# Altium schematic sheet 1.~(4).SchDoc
size 420 x 297 mm
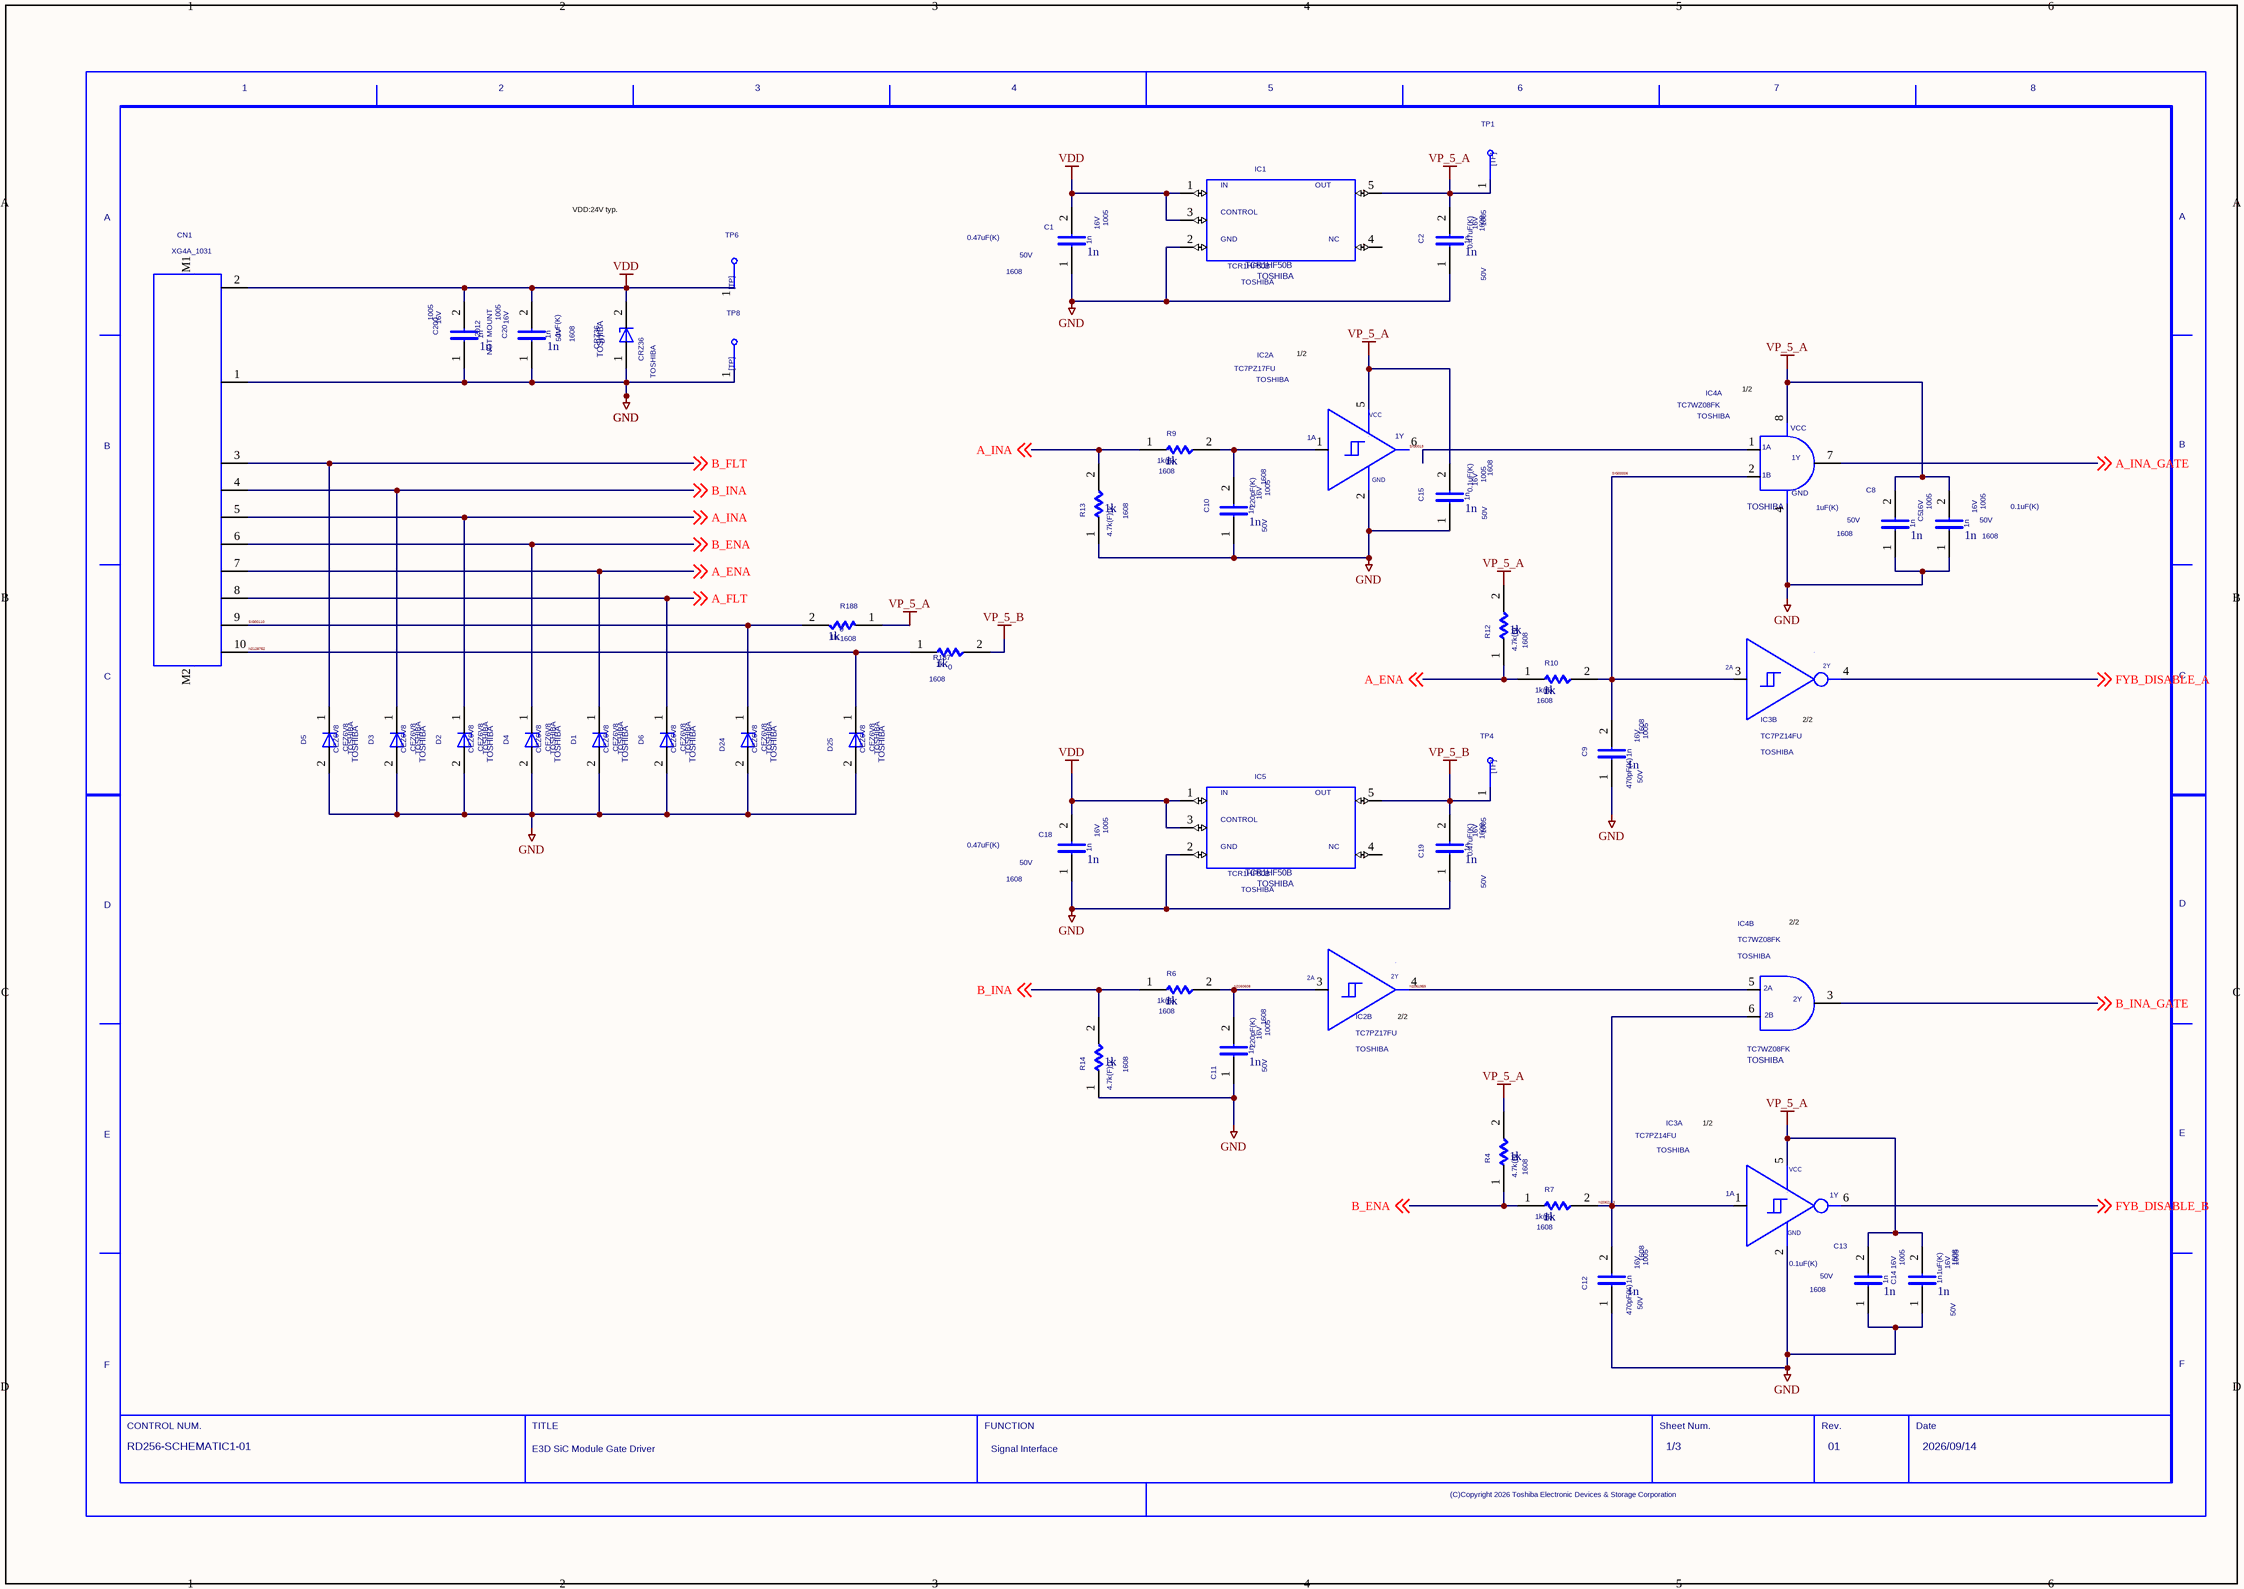
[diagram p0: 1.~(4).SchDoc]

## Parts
C1  1n  VAL1: 0.47uF(K)  SIZE: 1005  VOLTAGE: 16V  SIZECODESMD: 1608  VAL2: 50V
C2  1n  VAL1: 0.47uF(K)  SIZE: 1005  VOLTAGE: 16V  SIZECODESMD: 1608  VAL2: 50V
C5  1n  VAL1: 0.1uF(K)  SIZE: 1005  VOLTAGE: 16V  SIZECODESMD: 1608  VAL2: 50V
C8  1n  VAL1: 1uF(K)  SIZE: 1005  VOLTAGE: 16V  SIZECODESMD: 1608  VAL2: 50V
C9  1n  VAL1: 470pF(K)  SIZE: 1005  VOLTAGE: 16V  SIZECODESMD: 1608  VAL2: 50V
C10  1n  VAL1: 220pF(K)  SIZE: 1005  VOLTAGE: 16V  SIZECODESMD: 1608  VAL2: 50V
C11  1n  VAL1: 220pF(K)  SIZE: 1005  VOLTAGE: 16V  SIZECODESMD: 1608  VAL2: 50V
C12  1n  VAL1: 470pF(K)  SIZE: 1005  VOLTAGE: 16V  SIZECODESMD: 1608  VAL2: 50V
C13  1n  VAL1: 0.1uF(K)  SIZE: 1005  VOLTAGE: 16V  SIZECODESMD: 1608  VAL2: 50V
C14  1n  VAL1: 1uF(K)  SIZE: 1005  VOLTAGE: 16V  SIZECODESMD: 1608  VAL2: 50V
C15  1n  VAL1: 0.1uF(K)  SIZE: 1005  VOLTAGE: 16V  SIZECODESMD: 1608  VAL2: 50V
C18  1n  VAL1: 0.47uF(K)  SIZE: 1005  VOLTAGE: 16V  SIZECODESMD: 1608  VAL2: 50V
C19  1n  VAL1: 0.47uF(K)  SIZE: 1005  VOLTAGE: 16V  SIZECODESMD: 1608  VAL2: 50V
C20  1n  VAL1: 1uF(K)  SIZE: 1005  VOLTAGE: 16V  SIZECODESMD: 1608  VAL2: 50V
C200  1n  SIZE: 1005  VOLTAGE: 16V  SIZECODESMD: 2012  NOTMOUNT: NOT MOUNT
CN1  XG4A_1031
D1  CEZ6V8  VENDOR: TOSHIBA
D2  CEZ6V8  VENDOR: TOSHIBA
D3  CEZ6V8  VENDOR: TOSHIBA
D4  CEZ6V8  VENDOR: TOSHIBA
D5  CEZ6V8  VENDOR: TOSHIBA
D6  CEZ6V8  VENDOR: TOSHIBA
D7  CRZ36  VENDOR: TOSHIBA
D24  CEZ6V8  VENDOR: TOSHIBA
D25  CEZ6V8  VENDOR: TOSHIBA
IC1  TCR1HF50B  VENDOR: TOSHIBA
IC2  USERCOMPTEXT3: TOSHIBA  (hidden comment: TC7PZ17FU)  (parts A,B of 2)
IC3  USERCOMPTEXT3: TOSHIBA  VAL3: TC7PZ14FU  (hidden comment: TC7PZ17FU)  (parts A,B of 2)
IC4  VENDOR: TOSHIBA  (hidden comment: TC7WZ08FK)  (parts A,B of 2)
IC5  TCR1HF50B  VENDOR: TOSHIBA
R4  1k  VAL1: 4.7k(F)  SIZECODESMD: 1608
R6  1k  VAL1: 1k(F)  SIZECODESMD: 1608
R7  1k  VAL1: 1k(F)  SIZECODESMD: 1608
R9  1k  VAL1: 1k(F)  SIZECODESMD: 1608
R10  1k  VAL1: 1k(F)  SIZECODESMD: 1608
R12  1k  VAL1: 4.7k(F)  SIZECODESMD: 1608
R13  1k  VAL1: 4.7k(F)  SIZECODESMD: 1608
R14  1k  VAL1: 4.7k(F)  SIZECODESMD: 1608
R187  1k  VAL1: 0  SIZECODESMD: 1608
R188  1k  VAL1: 0  SIZECODESMD: 1608
TP1  TP  (value not drawn)
TP4  TP  (value not drawn)
TP6  TP  (value not drawn)
TP8  TP  (value not drawn)
U?  DATE: 2026/09/14  DRAWINGNUMBER: RD256-SCHEMATIC1-01  TITLE: E3D SiC Module Gate Driver  FUNCTION: Signal Interface  SHEETNUMBER: 1/3  REVISION: 01  (hidden comment: WAKU_DEF100)

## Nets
GND: C1.1 C2.1 C5.1 C8.1 C9.1 C10.1 C11.1 C12.1 C13.1 C14.1 C15.1 C18.1 C19.1 C20.1 C200.1 CN1.1 D1.2(A) D2.2(A) D3.2(A) D4.2(A) D5.2(A) D6.2(A) D7.1(A) D24.2(A) D25.2(A) IC1.2 IC2.2 IC3.2 IC4.4 IC5.2 R13.1 R14.1 TP8.1
VDD: C1.2 C18.2 C20.2 C200.2 CN1.2 D7.2(C) IC1.1 IC1.3 IC5.1 IC5.3 TP6.1
VP_5_A: C2.2 C5.2 C8.2 C13.2 C14.2 C15.2 IC1.5 IC2.5 IC3.5 IC4.8 R4.2 R12.2 R188.1 TP1.1
VP_5_B: C19.2 IC5.5 R187.2 TP4.1
A_ENA: CN1.7 D1.1(C) R10.1 R12.1 ; off-sheet A_ENA
A_FLT: CN1.8 D6.1(C) ; off-sheet A_FLT
A_INA: CN1.5 D2.1(C) R9.1 R13.2 ; off-sheet A_INA
A_INA_GATE: IC4.7 ; off-sheet A_INA_GATE
B_ENA: CN1.6 D4.1(C) R4.1 R7.1 ; off-sheet B_ENA
B_FLT: CN1.3 D5.1(C) ; off-sheet B_FLT
B_INA: CN1.4 D3.1(C) R6.1 R14.2 ; off-sheet B_INA
B_INA_GATE: IC4.3 ; off-sheet B_INA_GATE
FYB_DISABLE_A: IC3.4 ; off-sheet FYB_DISABLE_A
FYB_DISABLE_B: IC3.6 ; off-sheet FYB_DISABLE_B
N2060608: C11.2 IC2.3 R6.2
N2061959: IC2.4 IC4.5
N2062113: C12.2 IC3.1 IC4.6 R7.2
N2128752: CN1.10 D25.1(C) R187.1
SIG00006: C9.2 IC3.3 IC4.2 R10.2
SIG0013: IC2.6
SIG00110: CN1.9 D24.1(C) R188.2
SIG00237: C10.2 IC2.1 R9.2

Not connected (* = marked no-connect by the designer): CN1 M1 M2; IC1 4; IC4 1; IC5 4

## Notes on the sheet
- VDD:24V typ.
- 1/2
- (near IC4) 1/2
- (near IC3) 2/2
- 2/2
- (near IC2) 2/2
- (near IC3) 1/2

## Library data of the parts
C1 C18 = C: TIME: 11:55:01; UPDATEUSER: HP_Z8_KEYSHOT; SAVECOUNT: 2; TC1: 0; PSPICETEMPLATE: C^@REFDES %1 %2 ?TOLERANCE¦C^@REFDES¦ @VALUE ?IC/IC=@IC/ TC=@TC1,@TC2 ?TOLERANCE¦\n.model C^@REFDES CAP C=1 DEV=@TOLERANCE% TC1=@TC1 TC2=@TC2 VC1=@VC1 VC2=@VC2¦; ORIGINALSYMBOLORIGIN: (0,0); INSTANCENAME: INS1386363
C2 C19 = C: TIME: 11:55:01; UPDATEUSER: HP_Z8_KEYSHOT; SAVECOUNT: 2; TC1: 0; PSPICETEMPLATE: C^@REFDES %1 %2 ?TOLERANCE¦C^@REFDES¦ @VALUE ?IC/IC=@IC/ TC=@TC1,@TC2 ?TOLERANCE¦\n.model C^@REFDES CAP C=1 DEV=@TOLERANCE% TC1=@TC1 TC2=@TC2 VC1=@VC1 VC2=@VC2¦; ORIGINALSYMBOLORIGIN: (0,0); INSTANCENAME: INS1386331
C5 C14 C15 = C: TIME: 11:55:01; UPDATEUSER: HP_Z8_KEYSHOT; SAVECOUNT: 2; TC1: 0; PSPICETEMPLATE: C^@REFDES %1 %2 ?TOLERANCE¦C^@REFDES¦ @VALUE ?IC/IC=@IC/ TC=@TC1,@TC2 ?TOLERANCE¦\n.model C^@REFDES CAP C=1 DEV=@TOLERANCE% TC1=@TC1 TC2=@TC2 VC1=@VC1 VC2=@VC2¦; ORIGINALSYMBOLORIGIN: (0,0); INSTANCENAME: INS1386793
C8 C13 = C: TIME: 11:55:01; UPDATEUSER: HP_Z8_KEYSHOT; SAVECOUNT: 2; TC1: 0; PSPICETEMPLATE: C^@REFDES %1 %2 ?TOLERANCE¦C^@REFDES¦ @VALUE ?IC/IC=@IC/ TC=@TC1,@TC2 ?TOLERANCE¦\n.model C^@REFDES CAP C=1 DEV=@TOLERANCE% TC1=@TC1 TC2=@TC2 VC1=@VC1 VC2=@VC2¦; ORIGINALSYMBOLORIGIN: (0,0); INSTANCENAME: INS1386091
C9 C12 = C: TIME: 11:55:01; UPDATEUSER: HP_Z8_KEYSHOT; SAVECOUNT: 2; TC1: 0; PSPICETEMPLATE: C^@REFDES %1 %2 ?TOLERANCE¦C^@REFDES¦ @VALUE ?IC/IC=@IC/ TC=@TC1,@TC2 ?TOLERANCE¦\n.model C^@REFDES CAP C=1 DEV=@TOLERANCE% TC1=@TC1 TC2=@TC2 VC1=@VC1 VC2=@VC2¦; ORIGINALSYMBOLORIGIN: (0,0); INSTANCENAME: INS1386155
C10 C11 = C: TIME: 11:55:01; UPDATEUSER: HP_Z8_KEYSHOT; SAVECOUNT: 2; TC1: 0; PSPICETEMPLATE: C^@REFDES %1 %2 ?TOLERANCE¦C^@REFDES¦ @VALUE ?IC/IC=@IC/ TC=@TC1,@TC2 ?TOLERANCE¦\n.model C^@REFDES CAP C=1 DEV=@TOLERANCE% TC1=@TC1 TC2=@TC2 VC1=@VC1 VC2=@VC2¦; ORIGINALSYMBOLORIGIN: (0,0); INSTANCENAME: INS1386019
C20 = C: TIME: 11:55:01; UPDATEUSER: HP_Z8_KEYSHOT; SAVECOUNT: 2; TC1: 0; PSPICETEMPLATE: C^@REFDES %1 %2 ?TOLERANCE¦C^@REFDES¦ @VALUE ?IC/IC=@IC/ TC=@TC1,@TC2 ?TOLERANCE¦\n.model C^@REFDES CAP C=1 DEV=@TOLERANCE% TC1=@TC1 TC2=@TC2 VC1=@VC1 VC2=@VC2¦; ORIGINALSYMBOLORIGIN: (0,0); INSTANCENAME: INS1386685
C200 = C: TIME: 11:55:01; UPDATEUSER: HP_Z8_KEYSHOT; SAVECOUNT: 2; TC1: 0; PSPICETEMPLATE: C^@REFDES %1 %2 ?TOLERANCE¦C^@REFDES¦ @VALUE ?IC/IC=@IC/ TC=@TC1,@TC2 ?TOLERANCE¦\n.model C^@REFDES CAP C=1 DEV=@TOLERANCE% TC1=@TC1 TC2=@TC2 VC1=@VC1 VC2=@VC2¦; ORIGINALSYMBOLORIGIN: (0,0); INSTANCENAME: INS2126613
CN1 = XG4A_1031_1: PART NUMBER: XG4A-1031; TIME: 11:54:59; UPDATEUSER: t5459927; UPDATETIME: 17:44:51; SAVECOUNT: 12; PSPICETEMPLATE: X^@REFDES %1 %2 %3 %4 %5 %6 %7 %8 %9 %10 %M1 %M2 @MODEL; OriginalSymbolOrigin: (0,73660)
D1-D6 D24 D25 = CEZ6V8: TIME: 14:49:55; UPDATEUSER: fukuda-y; UPDATETIME: 08:18:42; SAVECOUNT: 6; SAVEAREA0: -4630,-153,17114,13055; PSPICETEMPLATE: X^@REFDES %A %C @MODEL; ORIGINALSYMBOLORIGIN: (0,0); INSTANCENAME: INS1385789
D7 = CRZ36: TIME: 14:49:55; UPDATEUSER: fukuda-y; UPDATETIME: 08:18:42; SAVECOUNT: 6; SAVEAREA0: -4630,-153,17114,13055; PSPICETEMPLATE: X^@REFDES %A %C @MODEL; ORIGINALSYMBOLORIGIN: (0,0); INSTANCENAME: INS1385571
IC1 IC5 = TCR1HF50B: TIME: 11:54:59; UPDATEUSER: t5459927; UPDATETIME: 10:27:35; SAVECOUNT: 4; PSPICETEMPLATE: X^@REFDES %IN %GND %CONTROL %NC %OUT @MODEL; OriginalSymbolOrigin: (-2540,0); INSTANCENAME: INS1386243
IC2 = TC7PZ17FU_2: TIME: 11:55:01; UPDATEUSER: t5459927; UPDATETIME: 15:05:08; SAVECOUNT: 4; SPLIT_INST: TRUE; PSPICETEMPLATE: X^@REFDES %1A %GND %2A %2Y %VCC %1Y @MODEL; SWAP_INFO: (S1+S2); OriginalSymbolOrigin: (5080,15240); CaptureCellPackProp: TC7PZ17FU_2A; FUNCN: TC7PZ17FU_1; INSTANCENAME: INS2115366
IC3 = TC7PZ14FU_2: TIME: 11:55:01; UPDATEUSER: t5459927; UPDATETIME: 19:09:34; SAVECOUNT: 7; SPLIT_INST: TRUE; PSPICETEMPLATE: X^@REFDES %1A %GND %2A %2Y %VCC %1Y @MODEL; SWAP_INFO: (S1+S2); OriginalSymbolOrigin: (5080,15240); CaptureCellPackProp: TC7PZ14FU_2A; FUNCN: TC7PZ14FU_1; INSTANCENAME: INS2115979
IC4 = TC7WZ08FK_1: TIME: 08:52:39; UPDATEUSER: sptcae09; UPDATETIME: 16:09:46; SAVECOUNT: 9; SWAP_INFO: (S1+S2); ORDER: $pOrder; SPLIT_INST: TRUE; ・: 20mA; USER_VALUE: TC7W00FK; PSPICETEMPLATE: X^@REFDES %1A %1B %2Y %GND %2A %2B %1Y %VCC @MODEL; DESCRIPTION-A: NAND 2ch Logic; ORIGINALSYMBOLORIGIN: (2540,-2540); CaptureCellPackProp: TC7WZ08FK_1A; INSTANCENAME: INS2116618
R4 R6 R7 R9 R10 R12 = R_Dup1: TIME: 11:54:58; UPDATEUSER: HP_Z8_KEYSHOT; UPDATETIME: 11:54:59; SAVECOUNT: 2; WATT: 0.125; COMP: R; TC1: 0; PSPICETEMPLATE: R^@REFDES %1 %2 ?TOLERANCE¦R^@REFDES¦ @VALUE TC=@TC1,@TC2 ?TOLERANCE¦\n.model R^@REFDES RES R=1 DEV=@TOLERANCE% TC1=@TC1 TC2=@TC2¦; ORIGINALSYMBOLORIGIN: (0,0); VAL2: 100mW; INSTANCENAME: INS1387005
R13 R14 = R_Dup1: TIME: 11:54:58; UPDATEUSER: HP_Z8_KEYSHOT; UPDATETIME: 11:54:59; SAVECOUNT: 2; WATT: 0.125; COMP: R; TC1: 0; PSPICETEMPLATE: R^@REFDES %1 %2 ?TOLERANCE¦R^@REFDES¦ @VALUE TC=@TC1,@TC2 ?TOLERANCE¦\n.model R^@REFDES RES R=1 DEV=@TOLERANCE% TC1=@TC1 TC2=@TC2¦; ORIGINALSYMBOLORIGIN: (0,0); VAL2: 100mW; INSTANCENAME: INS2060849
R187 = R_Dup1: TIME: 11:54:58; UPDATEUSER: HP_Z8_KEYSHOT; UPDATETIME: 11:54:59; SAVECOUNT: 2; WATT: 0.125; COMP: R; PSPICETEMPLATE: R^@REFDES %1 %2 ?TOLERANCE¦R^@REFDES¦ @VALUE TC=@TC1,@TC2 ?TOLERANCE¦\n.model R^@REFDES RES R=1 DEV=@TOLERANCE% TC1=@TC1 TC2=@TC2¦; ORIGINALSYMBOLORIGIN: (0,0); INSTANCENAME: INS2126667
R188 = R_Dup1: TIME: 11:54:58; UPDATEUSER: HP_Z8_KEYSHOT; UPDATETIME: 11:54:59; SAVECOUNT: 2; WATT: 0.125; COMP: R; PSPICETEMPLATE: R^@REFDES %1 %2 ?TOLERANCE¦R^@REFDES¦ @VALUE TC=@TC1,@TC2 ?TOLERANCE¦\n.model R^@REFDES RES R=1 DEV=@TOLERANCE% TC1=@TC1 TC2=@TC2¦; ORIGINALSYMBOLORIGIN: (0,0); INSTANCENAME: INS2126643
TP1 = TP: TIME: 16:12:21; UPDATEUSER: fukuda-y; UPDATETIME: 16:18:11; SAVECOUNT: 2; SAVEAREA0: -242,-92,12810,7836; ORIGINALSYMBOLORIGIN: (0,0); INSTANCENAME: INS1385435
TP4 = TP: TIME: 16:12:21; UPDATEUSER: fukuda-y; UPDATETIME: 16:18:11; SAVECOUNT: 2; SAVEAREA0: -242,-92,12810,7836; ORIGINALSYMBOLORIGIN: (0,0); INSTANCENAME: INS2191044
TP6 = TP: TIME: 16:12:21; UPDATEUSER: fukuda-y; UPDATETIME: 16:18:11; SAVECOUNT: 2; SAVEAREA0: -242,-92,12810,7836; ORIGINALSYMBOLORIGIN: (0,0); INSTANCENAME: INS1386079
TP8 = TP: TIME: 16:12:21; UPDATEUSER: fukuda-y; UPDATETIME: 16:18:11; SAVECOUNT: 2; SAVEAREA0: -242,-92,12810,7836; ORIGINALSYMBOLORIGIN: (0,0); INSTANCENAME: INS1386853
U? = WAKU_DEF100: PLOTTIME: HH:MM; SAVEAREA0: -63393,-16950,474261,314592; TIME: 14:30:25; UPDATEUSER: d5009410; UPDATETIME: 15:37:05; SAVECOUNT: 4; OriginalSymbolOrigin: (10160,284480); SHTSAVECOUNT: 49; NUMBER DEVICES IN PACKAGE: 1; SHEET NUM: X/X; PIN NUMBERS VISIBLE: False; CONTROL NUM: RD256-SCHEMATIC-0; PIN NAMES ROTATE: True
